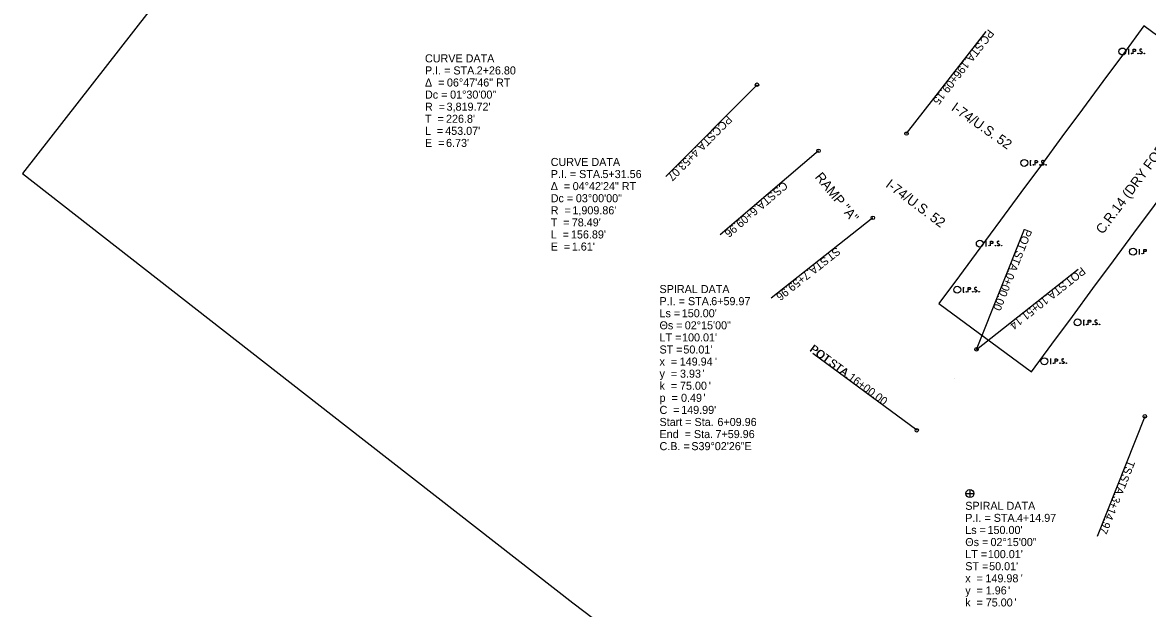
# Model space of a CAD drawing. Extents: x 1323342 to 1326901, y 458396 to 461756.
# Drawn here: x 1323342 to 1325299, y 459423 to 460441 of the extents above; entities that cross this region are included whole.
import ezdxf

# ---------------------------------------------------------------- set-up
doc = ezdxf.new("R2010")
doc.units = 0
for name, color, linetype in [('_CIVIL_CONSTRUCTION', 7, 'Continuous'), ('GE_P_Alignment_500_Cardinal_Points', 7, 'Continuous'), ('GE_X_Alignment_500_Cardinal_Points', 7, 'Continuous'), ('GE_X_Alignment_500_Curve_Data', 7, 'Continuous'), ('RD_X_Text', 7, 'Continuous'), ('SH_Named_Boundary', 7, 'Continuous'), ('SV_P_Mon_Cells_Set', 7, 'Continuous')]:
    doc.layers.add(name, color=color, linetype=linetype)

msp = doc.modelspace()

# ---------------------------------------------------------------- linework, layer by layer
at = {"layer": '_CIVIL_CONSTRUCTION'}
msp.add_circle((1324963.4, 459822.2), 0.05, dxfattribs=at)
at = {"layer": 'GE_P_Alignment_500_Cardinal_Points'}
msp.add_line((1324897.3, 459732.7), (1324716.4, 459866.4), dxfattribs=at)
msp.add_circle((1324897.3, 459732.7), 3, dxfattribs=at)
at = {"layer": 'GE_X_Alignment_500_Cardinal_Points'}
for p, q in [((1324879.5, 460248.4), (1325017.9, 460425.8)), ((1324619.6, 460333.4), (1324461.2, 460173.6)), ((1324726.4, 460218.5), (1324555.4, 460072.2)), ((1324820.9, 460102), (1324644.3, 459962.6)), ((1325001.3, 459873.4), (1325084.5, 460082.5)), ((1325001.3, 459873.4), (1325177.9, 460012.9)), ((1324897.3, 459732.7), (1324716.4, 459866.4)), ((1325294, 459757), (1325210.8, 459548))]:
    msp.add_line(p, q, dxfattribs=at)
for centre in [(1324619.6, 460333.4), (1324879.5, 460248.4), (1324726.4, 460218.5), (1324820.9, 460102), (1325001.3, 459873.4), (1325001.3, 459873.4), (1325294, 459757), (1324897.3, 459732.7)]:
    msp.add_circle(centre, 3, dxfattribs=at)
at = {"layer": 'SH_Named_Boundary'}
for points in [[(1324572.3, 461756.3), (1323342.2, 460179.3), (1323902.4, 459742.4), (1324099.5, 459588.6), (1324299.3, 459432.8), (1324514.7, 459269.4), (1324733.4, 459110.5), (1324955.2, 458956), (1325179.8, 458806.3), (1325389.2, 458669.7), (1325598.5, 458533.1), (1325807.9, 458396.4), (1326900.9, 460071.4), (1326691.5, 460208), (1326482.2, 460344.6), (1326272.8, 460481.2), (1326081.3, 460608.8), (1325892.9, 460740.1), (1325707.1, 460875.1), (1325524.2, 461013.9), (1325329.6, 461165.5), (1325132.5, 461319.3)], [(1324935.7, 459953), (1325096.6, 459834.1), (1325132.3, 459882.4), (1325167.9, 459930.6), (1325203.6, 459978.9), (1325239.2, 460027.2), (1325274.9, 460075.4), (1325310.5, 460123.7), (1325346.2, 460171.9), (1325381.8, 460220.2), (1325417.5, 460268.4), (1325453.2, 460316.7), (1325292.3, 460435.5), (1325256.6, 460387.3), (1325221, 460339), (1325185.3, 460290.8), (1325149.7, 460242.5), (1325114, 460194.3), (1325078.4, 460146), (1325042.7, 460097.8), (1325007.1, 460049.5), (1324971.4, 460001.2)]]:
    msp.add_lwpolyline(points, close=True, dxfattribs=at)
at = {"layer": 'SV_P_Mon_Cells_Set'}
for p, q in [((1324982.6, 459622.8), (1324996.7, 459622.8)), ((1324989.7, 459629.8), (1324989.7, 459615.7))]:
    msp.add_line(p, q, dxfattribs=at)
for points in [[(1325265.1, 460395.1), (1325266.9, 460395.1)], [(1325265.1, 460387.1), (1325266.9, 460387.1)], [(1325266, 460387.1), (1325266, 460395.1)], [(1325270.8, 460388.2), (1325271, 460388.2), (1325271.2, 460388.1), (1325271.4, 460387.8), (1325271.4, 460387.5), (1325271.2, 460387.3), (1325271, 460387.1), (1325270.8, 460387.1), (1325270.6, 460387.3), (1325270.4, 460387.5), (1325270.4, 460387.8), (1325270.6, 460388.1), (1325270.8, 460388.2)], [(1325273.8, 460387.1), (1325273.8, 460395.1), (1325276.4, 460395.1), (1325276.7, 460395.1), (1325277.1, 460395), (1325277.3, 460394.8), (1325277.4, 460394.7), (1325277.7, 460394.4), (1325277.8, 460394.1), (1325277.9, 460393.6), (1325277.9, 460392.8), (1325277.9, 460392.6), (1325277.8, 460392.2), (1325277.5, 460391.7), (1325277.3, 460391.6), (1325277.2, 460391.4), (1325276.9, 460391.3), (1325276.4, 460391.2), (1325273.8, 460391.2)], [(1325282, 460388.2), (1325282.3, 460388.2), (1325282.4, 460388.1), (1325282.6, 460387.8), (1325282.6, 460387.5), (1325282.4, 460387.3), (1325282.3, 460387.1), (1325282, 460387.1), (1325281.8, 460387.3), (1325281.7, 460387.5), (1325281.7, 460387.8), (1325281.8, 460388.1), (1325282, 460388.2)], [(1325288.8, 460394.6), (1325288.7, 460394.7), (1325288.6, 460394.8), (1325288.1, 460395), (1325287.5, 460395.1), (1325287, 460395.1), (1325286.9, 460395.1), (1325286.1, 460395), (1325285.5, 460394.6), (1325285.1, 460394.1), (1325285, 460393.6), (1325285, 460393.2), (1325285.1, 460392.7), (1325285.6, 460392.2), (1325288.6, 460390.4), (1325288.9, 460390.1), (1325289, 460389.9), (1325289.1, 460389.5), (1325289.1, 460389.1), (1325289.1, 460388.7), (1325289, 460388.5), (1325288.9, 460388.2), (1325288.8, 460387.9), (1325288.7, 460387.7), (1325288.5, 460387.5), (1325288.3, 460387.4), (1325288.1, 460387.3), (1325288, 460387.2), (1325287.5, 460387.1), (1325286.7, 460387.1), (1325286.2, 460387.3), (1325285.5, 460387.7), (1325285, 460388.1)], [(1325292.9, 460388.2), (1325293.2, 460388.2), (1325293.4, 460388.1), (1325293.5, 460387.8), (1325293.5, 460387.5), (1325293.4, 460387.3), (1325293.2, 460387.1), (1325292.9, 460387.1), (1325292.8, 460387.3), (1325292.6, 460387.5), (1325292.6, 460387.8), (1325292.8, 460388.1), (1325292.9, 460388.2)], [(1325094.4, 460201.5), (1325096.1, 460201.5)], [(1325094.4, 460193.5), (1325096.1, 460193.5)], [(1325095.2, 460193.5), (1325095.2, 460201.5)], [(1325100, 460194.6), (1325100.3, 460194.6), (1325100.5, 460194.5), (1325100.7, 460194.2), (1325100.7, 460193.9), (1325100.5, 460193.6), (1325100.3, 460193.5), (1325100, 460193.5), (1325099.9, 460193.6), (1325099.7, 460193.9), (1325099.7, 460194.2), (1325099.9, 460194.5), (1325100, 460194.6)], [(1325103.1, 460193.5), (1325103.1, 460201.5), (1325105.7, 460201.5), (1325106, 460201.4), (1325106.4, 460201.3), (1325106.5, 460201.2), (1325106.7, 460201.1), (1325106.9, 460200.8), (1325107.1, 460200.4), (1325107.2, 460199.9), (1325107.2, 460199.2), (1325107.2, 460198.9), (1325107, 460198.6), (1325106.8, 460198.1), (1325106.6, 460197.9), (1325106.4, 460197.8), (1325106.2, 460197.7), (1325105.7, 460197.6), (1325103.1, 460197.6)], [(1325111.3, 460194.6), (1325111.6, 460194.6), (1325111.7, 460194.5), (1325111.9, 460194.2), (1325111.9, 460193.9), (1325111.7, 460193.6), (1325111.6, 460193.5), (1325111.3, 460193.5), (1325111.1, 460193.6), (1325111, 460193.9), (1325111, 460194.2), (1325111.1, 460194.5), (1325111.3, 460194.6)], [(1325118.1, 460200.9), (1325118, 460201.1), (1325117.8, 460201.2), (1325117.4, 460201.4), (1325116.7, 460201.5), (1325116.3, 460201.5), (1325116.1, 460201.5), (1325115.4, 460201.3), (1325114.8, 460200.9), (1325114.4, 460200.4), (1325114.3, 460199.9), (1325114.3, 460199.6), (1325114.4, 460199.1), (1325114.9, 460198.6), (1325117.9, 460196.7), (1325118.2, 460196.5), (1325118.3, 460196.2), (1325118.4, 460195.8), (1325118.4, 460195.5), (1325118.3, 460195.1), (1325118.3, 460194.8), (1325118.2, 460194.5), (1325118.1, 460194.3), (1325118, 460194.1), (1325117.8, 460193.9), (1325117.6, 460193.8), (1325117.4, 460193.6), (1325117.2, 460193.6), (1325116.7, 460193.5), (1325116, 460193.5), (1325115.5, 460193.6), (1325114.8, 460194.1), (1325114.3, 460194.5)], [(1325122.2, 460194.6), (1325122.5, 460194.6), (1325122.6, 460194.5), (1325122.8, 460194.2), (1325122.8, 460193.9), (1325122.6, 460193.6), (1325122.5, 460193.5), (1325122.2, 460193.5), (1325122, 460193.6), (1325121.9, 460193.9), (1325121.9, 460194.2), (1325122, 460194.5), (1325122.2, 460194.6)], [(1325017.1, 460061.2), (1325018.8, 460061.2)], [(1325017.1, 460053.2), (1325018.8, 460053.2)], [(1325017.9, 460053.2), (1325017.9, 460061.2)], [(1325022.7, 460054.2), (1325023, 460054.2), (1325023.2, 460054.1), (1325023.3, 460053.9), (1325023.3, 460053.5), (1325023.2, 460053.3), (1325023, 460053.2), (1325022.7, 460053.2), (1325022.6, 460053.3), (1325022.4, 460053.5), (1325022.4, 460053.9), (1325022.6, 460054.1), (1325022.7, 460054.2)], [(1325025.8, 460053.2), (1325025.8, 460061.2), (1325028.4, 460061.2), (1325028.7, 460061.1), (1325029.1, 460061), (1325029.2, 460060.8), (1325029.4, 460060.7), (1325029.6, 460060.4), (1325029.8, 460060.1), (1325029.9, 460059.6), (1325029.9, 460058.8), (1325029.9, 460058.6), (1325029.7, 460058.2), (1325029.5, 460057.8), (1325029.3, 460057.6), (1325029.1, 460057.4), (1325028.9, 460057.3), (1325028.4, 460057.3), (1325025.8, 460057.3)], [(1325034, 460054.2), (1325034.3, 460054.2), (1325034.4, 460054.1), (1325034.6, 460053.9), (1325034.6, 460053.5), (1325034.4, 460053.3), (1325034.3, 460053.2), (1325034, 460053.2), (1325033.8, 460053.3), (1325033.7, 460053.5), (1325033.7, 460053.9), (1325033.8, 460054.1), (1325034, 460054.2)], [(1325040.8, 460060.6), (1325040.7, 460060.7), (1325040.5, 460060.8), (1325040, 460061), (1325039.4, 460061.2), (1325039, 460061.2), (1325038.8, 460061.2), (1325038.1, 460061), (1325037.5, 460060.6), (1325037.1, 460060.1), (1325037, 460059.6), (1325037, 460059.2), (1325037.1, 460058.7), (1325037.6, 460058.3), (1325040.6, 460056.4), (1325040.9, 460056.1), (1325041, 460055.9), (1325041.1, 460055.5), (1325041.1, 460055.1), (1325041, 460054.7), (1325041, 460054.5), (1325040.9, 460054.2), (1325040.8, 460053.9), (1325040.7, 460053.7), (1325040.5, 460053.5), (1325040.3, 460053.4), (1325040.1, 460053.3), (1325039.9, 460053.2), (1325039.4, 460053.2), (1325038.7, 460053.2), (1325038.2, 460053.3), (1325037.5, 460053.7), (1325037, 460054.1)], [(1325044.9, 460054.2), (1325045.2, 460054.2), (1325045.3, 460054.1), (1325045.5, 460053.9), (1325045.5, 460053.5), (1325045.3, 460053.3), (1325045.2, 460053.2), (1325044.9, 460053.2), (1325044.7, 460053.3), (1325044.6, 460053.5), (1325044.6, 460053.9), (1325044.7, 460054.1), (1325044.9, 460054.2)], [(1325283.6, 460047.2), (1325285.4, 460047.2)], [(1325284.5, 460039.2), (1325284.5, 460047.2)], [(1325292.3, 460039.2), (1325292.3, 460047.2), (1325295, 460047.2), (1325295.3, 460047.1), (1325295.7, 460047), (1325295.8, 460046.9), (1325296, 460046.7), (1325296.2, 460046.4), (1325296.4, 460046.1), (1325296.5, 460045.6), (1325296.5, 460044.8), (1325296.4, 460044.6), (1325296.3, 460044.2), (1325296.1, 460043.8), (1325295.9, 460043.6), (1325295.7, 460043.5), (1325295.4, 460043.3), (1325295, 460043.3), (1325292.3, 460043.3)], [(1325283.6, 460039.2), (1325285.4, 460039.2)], [(1325289.3, 460040.2), (1325289.6, 460040.2), (1325289.8, 460040.1), (1325289.9, 460039.9), (1325289.9, 460039.5), (1325289.8, 460039.3), (1325289.6, 460039.2), (1325289.3, 460039.2), (1325289.2, 460039.3), (1325289, 460039.5), (1325289, 460039.9), (1325289.2, 460040.1), (1325289.3, 460040.2)], [(1324977.8, 459981.1), (1324979.5, 459981.1)], [(1324977.8, 459973.1), (1324979.5, 459973.1)], [(1324978.7, 459973.1), (1324978.7, 459981.1)], [(1324983.5, 459974.2), (1324983.7, 459974.2), (1324983.9, 459974), (1324984.1, 459973.8), (1324984.1, 459973.5), (1324983.9, 459973.2), (1324983.7, 459973.1), (1324983.5, 459973.1), (1324983.3, 459973.2), (1324983.1, 459973.5), (1324983.1, 459973.8), (1324983.3, 459974), (1324983.5, 459974.2)], [(1324986.5, 459973.1), (1324986.5, 459981.1), (1324989.1, 459981.1), (1324989.4, 459981), (1324989.8, 459980.9), (1324990, 459980.8), (1324990.1, 459980.7), (1324990.4, 459980.3), (1324990.5, 459980), (1324990.6, 459979.5), (1324990.6, 459978.8), (1324990.6, 459978.5), (1324990.5, 459978.1), (1324990.2, 459977.7), (1324990, 459977.5), (1324989.9, 459977.4), (1324989.6, 459977.3), (1324989.1, 459977.2), (1324986.5, 459977.2)], [(1324994.7, 459974.2), (1324995, 459974.2), (1324995.1, 459974), (1324995.3, 459973.8), (1324995.3, 459973.5), (1324995.1, 459973.2), (1324995, 459973.1), (1324994.7, 459973.1), (1324994.5, 459973.2), (1324994.4, 459973.5), (1324994.4, 459973.8), (1324994.5, 459974), (1324994.7, 459974.2)], [(1325001.5, 459980.5), (1325001.4, 459980.7), (1325001.3, 459980.8), (1325000.8, 459981), (1325000.2, 459981.1), (1324999.7, 459981.1), (1324999.6, 459981.1), (1324998.8, 459980.9), (1324998.2, 459980.5), (1324997.8, 459980), (1324997.7, 459979.5), (1324997.7, 459979.1), (1324997.8, 459978.6), (1324998.3, 459978.2), (1325001.3, 459976.3), (1325001.6, 459976.1), (1325001.7, 459975.8), (1325001.8, 459975.4), (1325001.8, 459975), (1325001.8, 459974.7), (1325001.7, 459974.4), (1325001.6, 459974.1), (1325001.5, 459973.8), (1325001.4, 459973.7), (1325001.2, 459973.5), (1325001, 459973.3), (1325000.8, 459973.2), (1325000.7, 459973.2), (1325000.2, 459973.1), (1324999.4, 459973.1), (1324998.9, 459973.2), (1324998.2, 459973.7), (1324997.7, 459974)], [(1325005.6, 459974.2), (1325005.9, 459974.2), (1325006.1, 459974), (1325006.2, 459973.8), (1325006.2, 459973.5), (1325006.1, 459973.2), (1325005.9, 459973.1), (1325005.6, 459973.1), (1325005.5, 459973.2), (1325005.3, 459973.5), (1325005.3, 459973.8), (1325005.5, 459974), (1325005.6, 459974.2)], [(1325187, 459924.3), (1325188.8, 459924.3)], [(1325187, 459916.3), (1325188.8, 459916.3)], [(1325187.9, 459916.3), (1325187.9, 459924.3)], [(1325192.7, 459917.3), (1325193, 459917.3), (1325193.2, 459917.2), (1325193.3, 459917), (1325193.3, 459916.7), (1325193.2, 459916.4), (1325193, 459916.3), (1325192.7, 459916.3), (1325192.6, 459916.4), (1325192.4, 459916.7), (1325192.4, 459917), (1325192.6, 459917.2), (1325192.7, 459917.3)], [(1325195.7, 459916.3), (1325195.7, 459924.3), (1325198.4, 459924.3), (1325198.7, 459924.2), (1325199.1, 459924.1), (1325199.2, 459924), (1325199.4, 459923.8), (1325199.6, 459923.5), (1325199.8, 459923.2), (1325199.9, 459922.7), (1325199.9, 459921.9), (1325199.8, 459921.7), (1325199.7, 459921.3), (1325199.5, 459920.9), (1325199.3, 459920.7), (1325199.1, 459920.6), (1325198.8, 459920.4), (1325198.4, 459920.4), (1325195.7, 459920.4)], [(1325204, 459917.3), (1325204.2, 459917.3), (1325204.4, 459917.2), (1325204.6, 459917), (1325204.6, 459916.7), (1325204.4, 459916.4), (1325204.2, 459916.3), (1325204, 459916.3), (1325203.8, 459916.4), (1325203.6, 459916.7), (1325203.6, 459917), (1325203.8, 459917.2), (1325204, 459917.3)], [(1325210.8, 459923.7), (1325210.7, 459923.8), (1325210.5, 459924), (1325210, 459924.1), (1325209.4, 459924.3), (1325209, 459924.3), (1325208.8, 459924.3), (1325208.1, 459924.1), (1325207.5, 459923.7), (1325207.1, 459923.2), (1325207, 459922.7), (1325207, 459922.3), (1325207.1, 459921.8), (1325207.5, 459921.4), (1325210.6, 459919.5), (1325210.9, 459919.2), (1325211, 459919), (1325211.1, 459918.6), (1325211.1, 459918.2), (1325211, 459917.8), (1325211, 459917.6), (1325210.9, 459917.3), (1325210.7, 459917), (1325210.6, 459916.8), (1325210.5, 459916.7), (1325210.3, 459916.5), (1325210.1, 459916.4), (1325209.9, 459916.3), (1325209.4, 459916.3), (1325208.6, 459916.3), (1325208.2, 459916.4), (1325207.4, 459916.8), (1325207, 459917.2)], [(1325214.9, 459917.3), (1325215.1, 459917.3), (1325215.3, 459917.2), (1325215.5, 459917), (1325215.5, 459916.7), (1325215.3, 459916.4), (1325215.1, 459916.3), (1325214.9, 459916.3), (1325214.7, 459916.4), (1325214.5, 459916.7), (1325214.5, 459917), (1325214.7, 459917.2), (1325214.9, 459917.3)], [(1325129.4, 459856.7), (1325131.2, 459856.7)], [(1325130.3, 459848.7), (1325130.3, 459856.7)], [(1325138.1, 459848.7), (1325138.1, 459856.7), (1325140.8, 459856.7), (1325141.1, 459856.6), (1325141.5, 459856.5), (1325141.6, 459856.4), (1325141.8, 459856.3), (1325142, 459855.9), (1325142.2, 459855.6), (1325142.3, 459855.1), (1325142.3, 459854.4), (1325142.2, 459854.1), (1325142.1, 459853.7), (1325141.9, 459853.3), (1325141.7, 459853.1), (1325141.5, 459853), (1325141.2, 459852.9), (1325140.8, 459852.8), (1325138.1, 459852.8)], [(1325153.2, 459856.1), (1325153.1, 459856.3), (1325152.9, 459856.4), (1325152.4, 459856.6), (1325151.8, 459856.7), (1325151.4, 459856.7), (1325151.2, 459856.7), (1325150.5, 459856.5), (1325149.9, 459856.1), (1325149.5, 459855.6), (1325149.4, 459855.1), (1325149.4, 459854.7), (1325149.5, 459854.2), (1325149.9, 459853.8), (1325153, 459851.9), (1325153.2, 459851.7), (1325153.4, 459851.4), (1325153.5, 459851), (1325153.5, 459850.7), (1325153.4, 459850.3), (1325153.4, 459850), (1325153.2, 459849.7), (1325153.1, 459849.5), (1325153, 459849.3), (1325152.9, 459849.1), (1325152.7, 459849), (1325152.5, 459848.8), (1325152.3, 459848.8), (1325151.8, 459848.7), (1325151, 459848.7), (1325150.5, 459848.8), (1325149.8, 459849.3), (1325149.4, 459849.6)], [(1325129.4, 459848.7), (1325131.2, 459848.7)], [(1325135.1, 459849.8), (1325135.4, 459849.8), (1325135.6, 459849.6), (1325135.7, 459849.4), (1325135.7, 459849.1), (1325135.6, 459848.8), (1325135.4, 459848.7), (1325135.1, 459848.7), (1325134.9, 459848.8), (1325134.8, 459849.1), (1325134.8, 459849.4), (1325134.9, 459849.6), (1325135.1, 459849.8)], [(1325146.4, 459849.8), (1325146.6, 459849.8), (1325146.8, 459849.6), (1325147, 459849.4), (1325147, 459849.1), (1325146.8, 459848.8), (1325146.6, 459848.7), (1325146.4, 459848.7), (1325146.2, 459848.8), (1325146, 459849.1), (1325146, 459849.4), (1325146.2, 459849.6), (1325146.4, 459849.8)], [(1325157.3, 459849.8), (1325157.5, 459849.8), (1325157.7, 459849.6), (1325157.9, 459849.4), (1325157.9, 459849.1), (1325157.7, 459848.8), (1325157.5, 459848.7), (1325157.3, 459848.7), (1325157.1, 459848.8), (1325156.9, 459849.1), (1325156.9, 459849.4), (1325157.1, 459849.6), (1325157.3, 459849.8)]]:
    msp.add_lwpolyline(points, dxfattribs=at)
for centre, radius in [((1325255, 460391.1), 6), ((1325084.3, 460197.5), 6), ((1325007, 460057.2), 6), ((1325273.5, 460043.2), 6), ((1324967.7, 459977.1), 6), ((1325176.9, 459920.3), 6), ((1325119.3, 459852.7), 6), ((1324989.7, 459622.8), 7.05)]:
    msp.add_circle(centre, radius, dxfattribs=at)

# ---------------------------------------------------------------- texts
at = {"layer": 'GE_P_Alignment_500_Cardinal_Points'}
for s, p in [('POT', (1324709.7, 459871.6)), (' STA. ', (1324738.7, 459850.2)), ('16+00.00', (1324776.7, 459822.1))]:
    msp.add_text(s, height=14, rotation=323.5406, dxfattribs=at).set_placement(p)
at = {"layer": 'GE_X_Alignment_500_Cardinal_Points'}
for s, rotation, p in [('PC', 232.0433, (1325022, 460430.8)), (' STA. ', 232.0433, (1325007.8, 460412.6)), ('196+09.15', 232.0433, (1324979.1, 460375.9)), ('PCC', 225.2472, (1324567.9, 460280.9)), (' STA. ', 225.2472, (1324543.4, 460256.2)), ('4+53.07', 225.2472, (1324510.6, 460223.1)), (' STA. ', 220.5405, (1324649, 460152.1)), ('CS', 220.5405, (1324665.6, 460166.2)), ('6+09.96', 220.5405, (1324613.6, 460121.8)), ('POT', 248.3044, (1325085.3, 460084.1)), ('ST', 218.2905, (1324757.6, 460051.8)), (' STA. ', 218.2905, (1324741.5, 460039)), (' STA. ', 248.3044, (1325072.2, 460051)), ('7+59.96', 218.2905, (1324704.9, 460010.2)), ('POT', 218.2905, (1325183.9, 460017.4)), ('0+00.00', 248.3044, (1325054.9, 460007.7)), (' STA. ', 218.2905, (1325155.9, 459995.3)), ('10+51.14', 218.2905, (1325119.3, 459966.4)), ('POT', 323.5406, (1324710.5, 459871)), (' STA. ', 323.5406, (1324739.2, 459849.8)), ('16+00.00', 323.5406, (1324776.7, 459822.1)), ('TS', 248.3044, (1325264.3, 459681.8)), (' STA. ', 248.3044, (1325256.7, 459662.7)), ('3+14.97', 248.3044, (1325239.4, 459619.4))]:
    msp.add_text(s, height=14, rotation=rotation, dxfattribs=at).set_placement(p)
at = {"layer": 'GE_X_Alignment_500_Curve_Data'}
for s, p in [('CURVE DATA', (1324042.1, 460372.2)), ('P.I. = STA. ', (1324042.1, 460351.2)), ('2+26.80', (1324132, 460351.2)), ('Δ  = ', (1324042.1, 460330.2)), ('06°47\'46" RT', (1324080.3, 460330.2)), ('Dc = ', (1324042.1, 460309.2)), ('01°30\'00"', (1324085.8, 460309.2)), ('R  = ', (1324042.1, 460288.2)), ("3,819.72'", (1324079.7, 460288.2)), ('T  = ', (1324042.1, 460267.2)), ("226.8'", (1324078.7, 460267.2)), ('L  = ', (1324042.1, 460246.2)), ("453.07'", (1324077.3, 460246.2)), ('E  = ', (1324042.1, 460225.2)), ("6.73'", (1324078.8, 460225.2)), ('CURVE DATA', (1324260.8, 460192.1)), ('P.I. = STA. ', (1324260.8, 460171.1)), ('5+31.56', (1324350.7, 460171.1)), ('Δ  = ', (1324260.8, 460150.1)), ('04°42\'24" RT', (1324299, 460150.1)), ('Dc = ', (1324260.8, 460129.1)), ('03°00\'00"', (1324304.5, 460129.1)), ('R  = ', (1324260.8, 460108.1)), ("1,909.86'", (1324298.5, 460108.1)), ('T  = ', (1324260.8, 460087.1)), ("78.49'", (1324297.4, 460087.1)), ('L  = ', (1324260.8, 460066.1)), ("156.89'", (1324296, 460066.1)), ('E  = ', (1324260.8, 460045.1)), ("1.61'", (1324297.5, 460045.1)), ('SPIRAL DATA', (1324450, 459971.2)), ('P.I. = STA. ', (1324450, 459950.2)), ('6+59.97', (1324539.9, 459950.2)), ('Ls = ', (1324450, 459929.2)), ("150.00'", (1324488.7, 459929.2)), ('Θs = ', (1324450, 459908.2)), ('02°15\'00"', (1324493.9, 459908.2)), ('LT = ', (1324450, 459887.2)), ("100.01'", (1324489.2, 459887.2)), ('ST = ', (1324450, 459866.2)), ("50.01'", (1324491.5, 459866.2)), ('x  = ', (1324450, 459845.2)), ('149.94', (1324485.1, 459845.2)), ("'", (1324546.4, 459845.2)), ('y  = ', (1324450, 459824.2)), ('3.93', (1324485.6, 459824.2)), ("'", (1324524.5, 459824.2)), ('k  = ', (1324450, 459803.2)), ('75.00', (1324485.6, 459803.2)), ("'", (1324535.7, 459803.2)), ('p  = ', (1324450, 459782.2)), ('0.49', (1324487.4, 459782.2)), ("'", (1324526.3, 459782.2)), ('C  = ', (1324450, 459761.2)), ("149.99'", (1324487.7, 459761.2)), ('Start = Sta. ', (1324450, 459740.2)), ('6+09.96', (1324550.7, 459740.2)), ('End  = Sta. ', (1324450, 459719.2)), ('7+59.96', (1324547.3, 459719.2)), ('C.B. = ', (1324450, 459698.2)), ('S39°02\'26"E', (1324505.3, 459698.2)), ('SPIRAL DATA', (1324981.7, 459594.5)), ('P.I. = STA. ', (1324981.7, 459573.5)), ('4+14.97', (1325071.6, 459573.5)), ('Ls = ', (1324981.7, 459552.5)), ("150.00'", (1325020.4, 459552.5)), ('Θs = ', (1324981.7, 459531.5)), ('02°15\'00"', (1325025.6, 459531.5)), ('LT = ', (1324981.7, 459510.5)), ("100.01'", (1325020.9, 459510.5)), ('ST = ', (1324981.7, 459489.5)), ("50.01'", (1325023.2, 459489.5)), ('149.98', (1325016.8, 459468.5)), ("'", (1325078.1, 459468.5)), ('x  = ', (1324981.7, 459468.5)), ('1.96', (1325017.3, 459447.5)), ("'", (1325056.3, 459447.5)), ('y  = ', (1324981.7, 459447.5)), ('k  = ', (1324981.7, 459426.5)), ('75.00', (1325017.3, 459426.5)), ("'", (1325067.4, 459426.5))]:
    msp.add_text(s, height=14, dxfattribs=at).set_placement(p)
at = {"layer": 'RD_X_Text'}
for s, rotation, p in [('I-74/U.S. 52 ', 324.7532, (1324956.1, 460290.1)), ('C.R.14 (DRY FORK RD.)', 53.4743, (1325220.9, 460072.4)), ('RAMP "A"', 309.2208, (1324719.4, 460172.5)), ('I-74/U.S. 52 ', 323.0984, (1324841.9, 460156.9))]:
    msp.add_text(s, height=17, rotation=rotation, dxfattribs=at).set_placement(p)

doc.saveas('drawing.dxf')
